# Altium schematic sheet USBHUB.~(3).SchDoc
size A
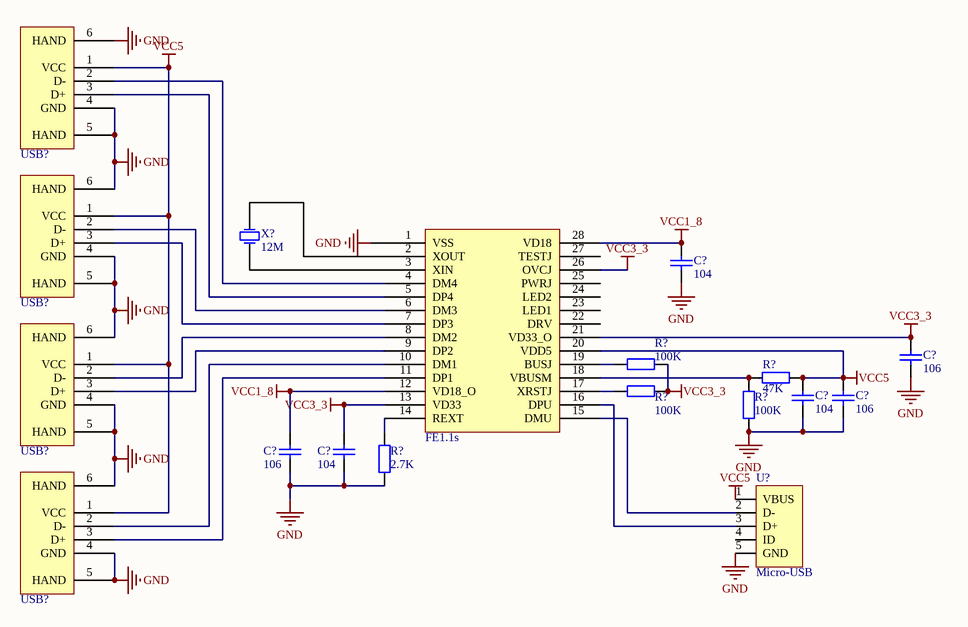
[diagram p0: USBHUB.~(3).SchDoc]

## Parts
(Parts that share a designator on the sheet are numbered #1, #2 ... from top to bottom, then left to right.)
C?#1  value 104  [2012[0805]-C]  (hidden comment: Cap1)
C?#2  value 106  [2012[0805]-C]  (hidden comment: Cap1)
C?#3  value 104  [2012[0805]-C]  (hidden comment: Cap1)
C?#4  value 106  [2012[0805]-C]  (hidden comment: Cap1)
C?#5  value 106  [2012[0805]-C]  (hidden comment: Cap1)
C?#6  value 104  [2012[0805]-C]  (hidden comment: Cap1)
FE1.1s  FE1.1s  [SSOP-28]  (value not drawn)
R?#1  value 100K  [2012[0805]-R]  (hidden comment: Res1)
R?#2  value 47K  [2012[0805]-R]  (hidden comment: Res1)
R?#3  value 100K  [2012[0805]-R]  (hidden comment: Res1)
R?#4  value 100K  [2012[0805]-R]  (hidden comment: Res1)
R?#5  value 2.7K  [2012[0805]-R]  (hidden comment: Res1)
U?  Micro-USB  [Micro-USB]
USB?#1  USB  [USB2.5-2V4A]  (value not drawn)
USB?#2  USB  [USB2.5-2V4A]  (value not drawn)
USB?#3  USB  [USB2.5-2V4A]  (value not drawn)
USB?#4  USB  [USB2.5-2V4A]  (value not drawn)
X?  12M  [XTAL]

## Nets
GND: C?#1.1 C?#2.1 C?#3.1 C?#4.1 C?#5.1 C?#6.1 R?#4.1 R?#5.1 U?.5(GND) USB?#1.4(GND) USB?#1.5(HAND) USB?#1.6(HAND) USB?#2.4(GND) USB?#2.5(HAND) USB?#2.6(HAND) USB?#3.4(GND) USB?#3.5(HAND) USB?#3.6(HAND) USB?#4.4(GND) USB?#4.5(HAND) USB?#4.6(HAND)
VCC1_8: C?#1.2 C?#5.2 FE1.1s.12(VD18_O) FE1.1s.28(VD18)
VCC3_3: C?#2.2 C?#6.2 FE1.1s.13(VD33) FE1.1s.21(VD33_O) FE1.1s.26(OVCJ) R?#1.2 R?#3.2
VCC5: C?#3.2 C?#4.2 FE1.1s.20(VDD5) R?#2.2 U?.1(VBUS) USB?#1.1(VCC) USB?#2.1(VCC) USB?#3.1(VCC) USB?#4.1(VCC)
NetFE1.1s_4: FE1.1s.4(DM4) USB?#1.2(D-)
NetFE1.1s_5: FE1.1s.5(DP4) USB?#1.3(D+)
NetFE1.1s_6: FE1.1s.6(DM3) USB?#2.2(D-)
NetFE1.1s_7: FE1.1s.7(DP3) USB?#2.3(D+)
NetFE1.1s_8: FE1.1s.8(DM2) USB?#3.2(D-)
NetFE1.1s_9: FE1.1s.9(DP2) USB?#3.3(D+)
NetFE1.1s_10: FE1.1s.10(DM1) USB?#4.2(D-)
NetFE1.1s_11: FE1.1s.11(DP1) USB?#4.3(D+)
NetFE1.1s_14: FE1.1s.14(REXT) R?#5.2
NetFE1.1s_15: FE1.1s.15(DMU) U?.2(D-)
NetFE1.1s_16: FE1.1s.16(DPU) U?.3(D+)
NetFE1.1s_17: FE1.1s.17(XRSTJ) R?#3.1
NetFE1.1s_18: FE1.1s.18(VBUSM) R?#2.1 R?#4.2
NetFE1.1s_19: FE1.1s.19(BUSJ) R?#1.1

Not connected (* = marked no-connect by the designer): FE1.1s 1(VSS) 2(XOUT) 3(XIN) 22(DRV) 23(LED1) 24(LED2) 25(PWRJ) 27(TESTJ); U? 4(ID); X? 1(OSC1) 2(OSC2)

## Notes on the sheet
- Labels drawn without touching a wire or pin: GND

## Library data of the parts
C?#1-C?#6 = Cap1: Capacitor
R?#1-R?#5 = Res1: Resistor
X? = XTAL_1: Crystal Oscillator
